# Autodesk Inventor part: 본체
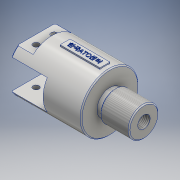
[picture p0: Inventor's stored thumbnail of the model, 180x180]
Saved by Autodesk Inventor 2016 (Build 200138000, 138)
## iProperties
Created: 2019-02
Part Number: 본체
Material: 알루미늄 6061
Document SubType Name: Modeling
Designer: 605-17
Density: 2.7 g/cm^3
Appearance: 알루미늄 - 평지
Mass: 345.889 g
Surface Area: 290.427 cm^2
Volume: 128.107 cm^3
Author: 605-17
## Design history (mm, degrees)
sketch "스케치1"
  geometry: L1 (0, 0)-(108, 0); L2 (74, 13)-(74, 28); L3 (73, 29)-(1, 29); L4 (0, 28)-(0, 0); L5 (36, 14)-(36, 0); L6 (36, 14)-(38.65, 14); L7 (38.65, 14)-(38.65, 16.2); L8 (39.45, 17)-(42.55, 17); L9 (43.35, 16.2)-(43.35, 14); L10 (43.35, 14)-(47.65, 14); L11 (47.65, 14)-(47.65, 16.2); L12 (48.45, 17)-(51.55, 17); L13 (52.35, 16.2)-(52.35, 14); L14 (52.35, 14)-(56, 14); L15 (56, 14)-(56, 16); L16 (56, 16)-(63, 16); L17 (63, 16)-(63, 4); L18 (41, 17)-(41, 0); L19 (50, 17)-(50, 0); L20 (73, 29)-(74, 28); L21 (74, 13)-(79, 13); L22 (79, 13)-(79, 15); L23 (79, 15)-(108, 15); L24 (108, 15)-(108, 0); L25 (63, 4)-(86, 4); L26 (86, 4)-(86, 0); L27 (0, 28)-(1, 29); A1 r 0.8 centre (39.45, 16.2) between (39.45, 17) and (38.65, 16.2); A2 r 0.8 centre (42.55, 16.2) between (43.35, 16.2) and (42.55, 17); A3 r 0.8 centre (48.45, 16.2) between (48.45, 17) and (47.65, 16.2); A4 r 0.8 centre (51.55, 16.2) between (52.35, 16.2) and (51.55, 17); 4 further points
  constraints: 54 end point, 17 point on line, 12 perpendicular, 8 point on circle, 8 tangent, 4 centre point, 4 parallel, 3 equal radius, 2 horizontal, 2 midpoint, 2 vertical
  dimensions: "d0" = 58 diameter of L3 L1; "d1" = 74 distance between parallel lines of L2 L4; "d2" = 36 distance between parallel lines of L5 L4; "d3" = 28 diameter of L6 L1; "d4" = 34 diameter of L8 L1; "d5" = 4.7 distance between parallel lines of L9 L7; "d6" = 4.7 distance between parallel lines of L13 L11; "d7" = 32 diameter of L16 L1; "d8" = 7 distance between parallel lines of L17 L15; "d9" = 5 distance from line of L18.start L5; "d10" = 9 distance of L19.start L18.start; "d11" = 27 distance between parallel lines of L17 L5; "d12" = 0.8 radius of A1; "d13" = 1 distance of L3.start point (74, 29); "d14" = 1 distance of L2.end point (74, 29) (= d13); "d15" = 26 diameter of L21 L1; "d16" = 34 distance between parallel lines of L24 L2; "d17" = 5 distance between parallel lines of L22 L2; "d18" = 30 diameter of L23 L1; "d19" = 8 diameter of L25 L1; "d20" = 22 distance between parallel lines of L26 L24; "d21" = 1 distance of L4.start point (0, 29); "d22" = 1 distance of L3.end point (0, 29) (= d21)
revolve "회전1" sketch "스케치1" stored, may be unused: angle "d23" = 90 deg
sketch "스케치2"
  geometry: L1 (15, -34.688)-(-15, -34.688); L2 (-15, -34.688)-(-15, 34.687); L3 (-15, 34.687)-(15, 34.688); L4 (15, 34.688)-(15, -34.688); L5 (15, -34.688)-(-15, 34.687); L6 (-15, -34.688)-(15, 34.688); L7 (-22, 38.152)-(-22, -44); L8 (22, 40.017)-(22, -47); L9 (-22, 38.152)-(-52.067, 38.152); L10 (-52.067, 38.152)-(-52.067, -44); L11 (-52.067, -44)-(-22, -44); L12 (22, 40.017)-(59.336, 40.017); L13 (59.336, 40.017)-(59.336, -47); L14 (59.336, -47)-(22, -47); C1 r 28 at (0, 0) reference; C2 r 29 at (0, 0) reference; 3 further points
  constraints: 28 end point, 8 parallel, 4 midpoint, 2 vertical, 1 horizontal, 1 perpendicular
  dimensions: "d24" = 30 distance between parallel lines of L4 L2; "d27" = 22 distance from line of point (0, 0) L7; "d28" = 22 distance from line of L8 point (0, 0)
extrude "돌출1" cut sketch "스케치2" distance "d29" = 36; taper "d30" = 0 deg
extrude "돌출2" cut sketch "스케치2" distance "d31" = 16; taper "d32" = 0 deg
chamfer "모따기1" distance "d33" = 1; stored, may be unused: second distance "d34" = 2, angle "d35" = 45 deg
sketch "스케치3"
  geometry: C1 r 15 at (0, 0) reference; 1 further point
hole "구멍1" sketch "스케치3" at (0, 0) diameter "d36" = 12.376; stored, may be unused: countersink angle "d40" = 90 deg, drill point angle "d42" = 118 deg; dims "d37" = 18, "d38" = 4, "d39" = 2, "d41" = 22
feature "스레드1" dims "d43" = 10, "d44" = 0
chamfer "모따기2" distance "d45" = 1; stored, may be unused: second distance "d46" = 2, angle "d47" = 45 deg
sketch "스케치4"
  geometry: L1 (0, 17.321)-(14, 17.321); C1 r 3 at (9, 26.321); C2 r 3 at (9, 8.321)
  constraints: 2 centre point, 2 end point, 1 horizontal, 1 vertical alignment
  dimensions: "d48" = 6 diameter of C1; "d49" = 6 diameter of C2; "d51" = 9 horizontal distance of C1.centre L1.start; "d52" = 18 diameter of C1.centre L1; "d53" = 18 diameter of C2.centre L1
extrude "돌출3" cut sketch "스케치4" stored distance "d54" = 16; taper "d55" = 0 deg
node "작업 평면1"
sketch "스케치5"
  geometry: L1 (69, -5)-(29, -5); L2 (29, -5)-(29, 5); L3 (29, 5)-(69, 5); L4 (69, 5)-(69, -5); L5 (69, -5)-(29, 5); L6 (29, -5)-(69, 5); L7 (74, -28)-(74, 28) reference; 4 further points
  constraints: 12 end point, 3 midpoint, 2 parallel, 1 horizontal, 1 horizontal alignment, 1 perpendicular, 1 other
  dimensions: "d57" = 40 distance between parallel lines of L4 L2; "d58" = 10 distance between parallel lines of L1 L3; "d59" = 5 distance between parallel lines of L7 L4; "d60" = 20 distance from line of point (49, 0) L2; "d61" = 5 distance from line of L1 point (49, 0)
extrude "돌출4" join sketch "스케치5" stored distance "d62" = 16; taper "d63" = 0 deg
feature "엠보싱1" dims "d64" = 0.5, "d65" = 0
node "솔리드1"
